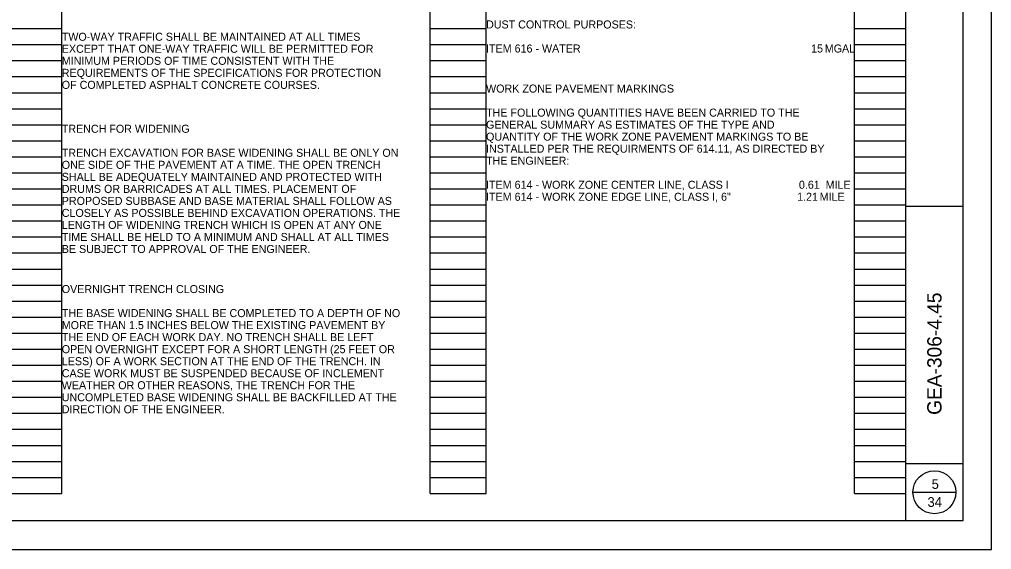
# Model space of a CAD drawing. Extents: x -16.4 to 17.6, y -12.9 to 9.1.
# Drawn here: x 0.63 to 17.63, y -12.91 to -3.65 of the extents above; entities that cross this region are included whole.
import ezdxf

# ---------------------------------------------------------------- set-up
doc = ezdxf.new("R2010")
doc.units = 0
for name, color, linetype in [('SH_Border', 7, 'Continuous'), ('SH_Cut_Line', 7, 'Continuous'), ('SH_Data', 7, 'Continuous'), ('SH_Text', 7, 'Continuous'), ('TX_P_1', 7, 'Continuous')]:
    doc.layers.add(name, color=color, linetype=linetype)

# ---------------------------------------------------------------- blocks, each defined once
blk = doc.blocks.new('4COL')
at = {"layer": 'SH_Data'}
for p, q in [((17.74, 0.98), (17.74, 21.14)), ((24.18, 0.98), (24.18, 21.14)), ((25.16, 0.98), (25.16, 21.14)), ((31.6, 0.98), (31.6, 21.14)), ((32.5, 0.98), (32.5, 21.14)), ((16.76, 9.1), (17.74, 9.1)), ((24.18, 9.1), (25.16, 9.1)), ((31.6, 9.1), (32.5, 9.1)), ((16.76, 8.82), (17.74, 8.82)), ((24.18, 8.82), (25.16, 8.82)), ((31.6, 8.82), (32.5, 8.82)), ((16.76, 8.54), (17.74, 8.54)), ((24.18, 8.54), (25.16, 8.54)), ((31.6, 8.54), (32.5, 8.54)), ((16.76, 8.26), (17.74, 8.26)), ((24.18, 8.26), (25.16, 8.26)), ((31.6, 8.26), (32.5, 8.26)), ((16.76, 7.98), (17.74, 7.98)), ((24.18, 7.98), (25.16, 7.98)), ((31.6, 7.98), (32.5, 7.98)), ((16.76, 7.7), (17.74, 7.7)), ((24.18, 7.7), (25.16, 7.7)), ((31.6, 7.7), (32.5, 7.7)), ((16.76, 7.42), (17.74, 7.42)), ((24.18, 7.42), (25.16, 7.42)), ((31.6, 7.42), (32.5, 7.42)), ((16.76, 7.14), (17.74, 7.14)), ((24.18, 7.14), (25.16, 7.14)), ((31.6, 7.14), (32.5, 7.14)), ((16.76, 6.86), (17.74, 6.86)), ((24.18, 6.86), (25.16, 6.86)), ((31.6, 6.86), (32.5, 6.86)), ((16.76, 6.58), (17.74, 6.58)), ((24.18, 6.58), (25.16, 6.58)), ((31.6, 6.58), (32.5, 6.58)), ((16.76, 6.3), (17.74, 6.3)), ((24.18, 6.3), (25.16, 6.3)), ((31.6, 6.3), (32.5, 6.3)), ((16.76, 6.02), (17.74, 6.02)), ((24.18, 6.02), (25.16, 6.02)), ((31.6, 6.02), (32.5, 6.02)), ((16.76, 5.74), (17.74, 5.74)), ((24.18, 5.74), (25.16, 5.74)), ((31.6, 5.74), (32.5, 5.74)), ((16.76, 5.46), (17.74, 5.46)), ((24.18, 5.46), (25.16, 5.46)), ((31.6, 5.46), (32.5, 5.46)), ((16.76, 5.18), (17.74, 5.18)), ((24.18, 5.18), (25.16, 5.18)), ((31.6, 5.18), (32.5, 5.18)), ((16.76, 4.9), (17.74, 4.9)), ((24.18, 4.9), (25.16, 4.9)), ((31.6, 4.9), (32.5, 4.9)), ((16.76, 4.62), (17.74, 4.62)), ((24.18, 4.62), (25.16, 4.62)), ((31.6, 4.62), (32.5, 4.62)), ((16.76, 4.34), (17.74, 4.34)), ((24.18, 4.34), (25.16, 4.34)), ((31.6, 4.34), (32.5, 4.34)), ((16.76, 4.06), (17.74, 4.06)), ((24.18, 4.06), (25.16, 4.06)), ((31.6, 4.06), (32.5, 4.06)), ((16.76, 3.78), (17.74, 3.78)), ((24.18, 3.78), (25.16, 3.78)), ((31.6, 3.78), (32.5, 3.78)), ((16.76, 3.5), (17.74, 3.5)), ((24.18, 3.5), (25.16, 3.5)), ((31.6, 3.5), (32.5, 3.5)), ((16.76, 3.22), (17.74, 3.22)), ((24.18, 3.22), (25.16, 3.22)), ((31.6, 3.22), (32.5, 3.22)), ((16.76, 2.94), (17.74, 2.94)), ((24.18, 2.94), (25.16, 2.94)), ((31.6, 2.94), (32.5, 2.94)), ((16.76, 2.66), (17.74, 2.66)), ((24.18, 2.66), (25.16, 2.66)), ((31.6, 2.66), (32.5, 2.66)), ((16.76, 2.38), (17.74, 2.38)), ((24.18, 2.38), (25.16, 2.38)), ((31.6, 2.38), (32.5, 2.38)), ((16.76, 2.1), (17.74, 2.1)), ((24.18, 2.1), (25.16, 2.1)), ((31.6, 2.1), (32.5, 2.1)), ((16.76, 1.82), (17.74, 1.82)), ((24.18, 1.82), (25.16, 1.82)), ((31.6, 1.82), (32.5, 1.82)), ((16.76, 1.54), (17.74, 1.54)), ((24.18, 1.54), (25.16, 1.54)), ((31.6, 1.54), (32.5, 1.54)), ((16.76, 1.26), (17.74, 1.26)), ((24.18, 1.26), (25.16, 1.26)), ((31.6, 1.26), (32.5, 1.26)), ((16.76, 0.98), (17.74, 0.98)), ((24.18, 0.98), (25.16, 0.98)), ((31.6, 0.98), (32.5, 0.98))]:
    blk.add_line(p, q, dxfattribs=at)

msp = doc.modelspace()

# ---------------------------------------------------------------- linework, layer by layer
at = {"layer": 'SH_Border'}
for p, q in [((16.129, -12.407), (16.129, 8.593)), ((16.129, -6.907), (17.129, -6.907)), ((16.129, -11.407), (17.129, -11.407))]:
    msp.add_line(p, q, dxfattribs=at)
msp.add_lwpolyline([(-14.371, 8.593), (17.129, 8.593), (17.129, -12.407), (-14.371, -12.407)], close=True, dxfattribs=at)
at = {"layer": 'SH_Cut_Line'}
msp.add_lwpolyline([(-16.371, -12.907), (17.629, -12.907), (17.629, 9.093), (-16.371, 9.093)], close=True, dxfattribs=at)
at = {"layer": 'SH_Data'}
msp.add_line((16.254, -11.907), (17.004, -11.907), dxfattribs=at)
msp.add_circle((16.629, -11.907), 0.375, dxfattribs=at)

# ---------------------------------------------------------------- block references
at = {"layer": 'SH_Text'}
msp.add_blockref('4COL', (-16.371, -12.907), dxfattribs=at)

# ---------------------------------------------------------------- texts
at = {"layer": 'SH_Data'}
msp.add_text('GEA-306-4.45', height=0.25, rotation=90, dxfattribs=at).set_placement((16.754, -10.555))
at = {"layer": 'SH_Text'}
for s, height, p in [('DUST CONTROL PURPOSES:', 0.14, (8.789, -3.805)), ('TWO-WAY TRAFFIC SHALL BE MAINTAINED AT ALL TIMES ', 0.14, (1.369, -4.02)), ('EXCEPT THAT ONE-WAY TRAFFIC WILL BE PERMITTED FOR ', 0.14, (1.369, -4.23)), ('ITEM 616 - WATER                              ', 0.14, (8.789, -4.225)), ('15', 0.14, (14.473, -4.225)), (' MGAL', 0.14, (14.66, -4.225)), ('MINIMUM PERIODS OF TIME CONSISTENT WITH THE ', 0.14, (1.369, -4.44)), ('REQUIREMENTS OF THE SPECIFICATIONS FOR PROTECTION', 0.14, (1.369, -4.65)), ('OF COMPLETED ASPHALT CONCRETE COURSES.', 0.14, (1.369, -4.86)), ('THE FOLLOWING QUANTITIES HAVE BEEN CARRIED TO THE ', 0.14, (8.789, -5.345)), ('GENERAL SUMMARY AS ESTIMATES OF THE TYPE AND ', 0.14, (8.789, -5.555)), ('QUANTITY OF THE WORK ZONE PAVEMENT MARKINGS TO BE ', 0.14, (8.789, -5.765)), ('TRENCH EXCAVATION FOR BASE WIDENING SHALL BE ONLY ON ', 0.14, (1.369, -6.047)), ('INSTALLED PER THE REQUIRMENTS OF 614.11, AS DIRECTED BY ', 0.14, (8.789, -5.975)), ('ONE SIDE OF THE PAVEMENT AT A TIME. THE OPEN TRENCH ', 0.14, (1.369, -6.257)), ('THE ENGINEER:', 0.14, (8.789, -6.185)), ('SHALL BE ADEQUATELY MAINTAINED AND PROTECTED WITH ', 0.14, (1.369, -6.467)), ('DRUMS OR BARRICADES AT ALL TIMES. PLACEMENT OF ', 0.14, (1.369, -6.677)), ('ITEM 614 - WORK ZONE CENTER LINE, CLASS I         ', 0.14, (8.789, -6.605)), ('0.61', 0.14, (14.26, -6.605)), (' MILE', 0.14, (14.675, -6.605)), ('PROPOSED SUBBASE AND BASE MATERIAL SHALL FOLLOW AS ', 0.14, (1.369, -6.887)), ('ITEM 614 - WORK ZONE EDGE LINE, CLASS I, 6"       ', 0.14, (8.789, -6.815)), ('1.21', 0.14, (14.229, -6.815)), (' MILE', 0.14, (14.571, -6.815)), ('CLOSELY AS POSSIBLE BEHIND EXCAVATION OPERATIONS. THE ', 0.14, (1.369, -7.097)), ('LENGTH OF WIDENING TRENCH WHICH IS OPEN AT ANY ONE ', 0.14, (1.369, -7.307)), ('TIME SHALL BE HELD TO A MINIMUM AND SHALL AT ALL TIMES ', 0.14, (1.369, -7.517)), ('BE SUBJECT TO APPROVAL OF THE ENGINEER.', 0.14, (1.369, -7.727)), ('THE BASE WIDENING SHALL BE COMPLETED TO A DEPTH OF NO ', 0.14, (1.369, -8.847)), ('MORE THAN 1.5 INCHES BELOW THE EXISTING PAVEMENT BY ', 0.14, (1.369, -9.057)), ('THE END OF EACH WORK DAY. NO TRENCH SHALL BE LEFT ', 0.14, (1.369, -9.267)), ('OPEN OVERNIGHT EXCEPT FOR A SHORT LENGTH (25 FEET OR ', 0.14, (1.369, -9.477)), ('LESS) OF A WORK SECTION AT THE END OF THE TRENCH. IN ', 0.14, (1.369, -9.687)), ('CASE WORK MUST BE SUSPENDED BECAUSE OF INCLEMENT ', 0.14, (1.369, -9.897)), ('WEATHER OR OTHER REASONS, THE TRENCH FOR THE ', 0.14, (1.369, -10.107)), ('UNCOMPLETED BASE WIDENING SHALL BE BACKFILLED AT THE ', 0.14, (1.369, -10.317)), ('DIRECTION OF THE ENGINEER.', 0.14, (1.369, -10.527)), ('5', 0.17, (16.581, -11.848)), ('34', 0.17, (16.508, -12.162))]:
    msp.add_text(s, height=height, dxfattribs=at).set_placement(p)
at = {"layer": 'TX_P_1'}
for s, p in [('WORK ZONE PAVEMENT MARKINGS', (8.789, -4.925)), ('TRENCH FOR WIDENING', (1.369, -5.627)), ('OVERNIGHT TRENCH CLOSING', (1.369, -8.427))]:
    msp.add_text(s, height=0.14, dxfattribs=at).set_placement(p)

doc.saveas('drawing.dxf')
